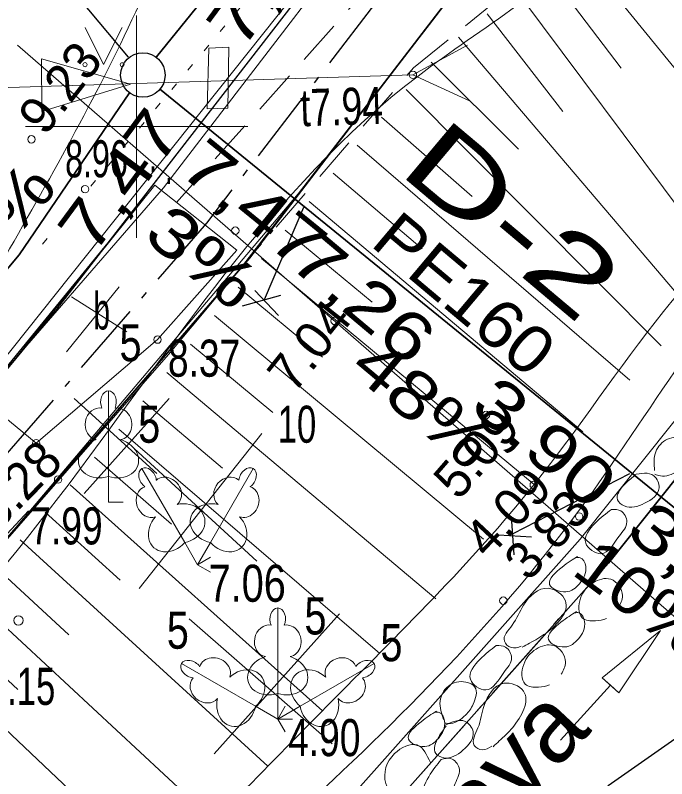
# Model space of a CAD drawing. Extents: x -1320 to -1174, y 762 to 862.
# Drawn here: x -1247.14 to -1238.36, y 811.79 to 822.09 of the extents above; entities that cross this region are included whole.
import ezdxf
from ezdxf.enums import TextEntityAlignment as Align

# ---------------------------------------------------------------- set-up
doc = ezdxf.new("R2010")
doc.units = 0
doc.header["$LTSCALE"] = 0.2
for name, pattern in [('DOT_DASHED', [7.7, 5, -1.2, 0.3, -1.2]), ('DOTTED', [1.5, 0.3, -1.2]), ('MEDIUM_DASHED', [4.5, 3, -1.5])]:
    doc.linetypes.add(name, pattern=pattern)
for name, color, linetype, lineweight in [('1', 7, 'Continuous', 13), ('11', 7, 'Continuous', 35), ('12', 7, 'Continuous', 13), ('19', 7, 'Continuous', 25), ('25', 7, 'Continuous', 13), ('28', 7, 'Continuous', 13), ('3', 7, 'Continuous', 13), ('30', 7, 'Continuous', 13), ('35', 7, 'Continuous', 25), ('4', 7, 'Continuous', 13), ('5', 7, 'Continuous', 13), ('55', 7, 'Continuous', 13), ('56', 7, 'Continuous', 13), ('57', 7, 'DOTTED', 13), ('6', 7, 'Continuous', 13), ('61', 7, 'Continuous', 13), ('62', 7, 'Continuous', 13), ('63', 7, 'Continuous', 13)]:
    doc.layers.add(name, color=color, linetype=linetype, lineweight=lineweight)
for name, color, linetype in [('15', 7, 'Continuous'), ('27', 7, 'Continuous'), ('8', 7, 'Continuous')]:
    doc.layers.add(name, color=color, linetype=linetype)

msp = doc.modelspace()

# ---------------------------------------------------------------- linework, layer by layer
at = {"layer": '1'}
for p, q in [((-1239.583, 823.017), (-1236.735, 819.506)), ((-1239.977, 822.71), (-1238.971, 821.376)), ((-1240.377, 822.41), (-1237.544, 818.612)), ((-1240.776, 822.109), (-1239.755, 820.789)), ((-1241.164, 821.793), (-1238.014, 818.09)), ((-1247.111, 821.685), (-1235.538, 811.611)), ((-1241.532, 821.455), (-1240.352, 820.28)), ((-1241.871, 821.088), (-1238.432, 817.627)), ((-1242.202, 820.713), (-1240.977, 819.642)), ((-1242.53, 820.335), (-1238.852, 817.164)), ((-1242.855, 819.955), (-1241.653, 818.938)), ((-1243.178, 819.573), (-1239.485, 816.469)), ((-1243.499, 819.19), (-1242.327, 818.215)), ((-1243.818, 818.805), (-1240.142, 815.757)), ((-1244.137, 818.42), (-1242.998, 817.476)), ((-1244.456, 818.036), (-1240.825, 815.021)), ((-1244.776, 817.651), (-1243.669, 816.729)), ((-1245.097, 817.268), (-1241.468, 814.213)), ((-1245.419, 816.885), (-1244.345, 815.976)), ((-1245.744, 816.505), (-1242.224, 813.478)), ((-1246.072, 816.127), (-1245.032, 815.219)), ((-1246.402, 815.753), (-1242.999, 812.703)), ((-1246.737, 815.381), (-1245.727, 814.465)), ((-1247.074, 815.011), (-1243.736, 811.955)), ((-1247.412, 814.643), (-1246.417, 813.726)), ((-1247.751, 814.276), (-1244.455, 811.216)), ((-1248.092, 813.91), (-1247.108, 812.991)), ((-1248.434, 813.546), (-1245.172, 810.47))]:
    msp.add_line(p, q, dxfattribs=at)
msp.add_spline([(-1235.8, 825.801), (-1237.913, 825.174), (-1239.203, 823.346), (-1241.709, 821.268), (-1246.557, 815.58), (-1256.526, 805.053), (-1260.592, 799.147), (-1261.416, 795.29), (-1262.742, 791.444), (-1262.206, 785.139)], degree=3, dxfattribs=at)
at = {"layer": '11'}
for points in [[(-1245.235, 821.525), (-1243.382, 823.815), (-1241.289, 826.563)], [(-1253.071, 812.055), (-1251.479, 813.616), (-1247.089, 818.854), (-1245.599, 821.041)]]:
    msp.add_lwpolyline(points, dxfattribs=at)
at = {"layer": '19', "lineweight": 13}
msp.add_spline([(-1253.457, 785.393), (-1253.726, 794.104), (-1251.637, 801.373), (-1250.122, 804.26), (-1247.608, 807.348), (-1239.437, 815.545), (-1236.508, 819.221), (-1228.799, 821.851), (-1223.357, 826.161), (-1220.079, 827.95)], degree=3, dxfattribs=at)
at = {"layer": '25'}
for points in [[(-1245.505, 822.086), (-1245.505, 820.586), (-1245.505, 819.086)], [(-1245.505, 822.086), (-1245.505, 820.586), (-1245.505, 819.086)], [(-1247.005, 820.586), (-1245.505, 820.586), (-1244.005, 820.586)], [(-1247.005, 820.586), (-1245.505, 820.586), (-1244.005, 820.586)]]:
    msp.add_lwpolyline(points, dxfattribs=at)
at = {"layer": '28'}
msp.add_lwpolyline([(-1241.04, 821.682), (-1241.778, 821.284), (-1241.017, 820.933)], dxfattribs=at)
at = {"layer": '3'}
msp.add_line((-1251.16, 820.99), (-1241.778, 821.284), dxfattribs=at)
at = {"layer": '30'}
msp.add_spline([(-1247.278, 818.829), (-1245.467, 822.244), (-1243.421, 828.633), (-1242.663, 831.887)], degree=3, dxfattribs=at)
at = {"layer": '35'}
msp.add_lwpolyline([(-1264.692, 791.666), (-1263.121, 794.463), (-1262.995, 800.82), (-1256.407, 807.512), (-1249.819, 814.203), (-1245.888, 819.015), (-1242.275, 823.687), (-1240.604, 825.846), (-1237.968, 829.25), (-1236.511, 829.583), (-1228.03, 831.521)], dxfattribs=at)
at = {"layer": '35', "lineweight": 35}
msp.add_lwpolyline([(-1225.362, 830.487), (-1237.056, 827.834), (-1243.981, 818.809), (-1250.833, 810.905), (-1258.147, 803.474), (-1260.339, 800.099), (-1261.472, 796.156), (-1261.529, 794.093), (-1263.29, 790.894)], dxfattribs=at)
at = {"layer": '4'}
msp.add_line((-1239.786, 812.309), (-1239.113, 813.048), dxfattribs=at)
for points in [[(-1238.439, 813.788), (-1239.002, 812.947), (-1239.224, 813.15)], [(-1239.113, 813.048), (-1239.002, 812.947), (-1238.439, 813.788), (-1239.224, 813.15)]]:
    msp.add_lwpolyline(points, close=True, dxfattribs=at)
at = {"layer": '5'}
for p, q in [((-1245.884, 817.019), (-1245.884, 815.866)), ((-1245.794, 816.787), (-1245.795, 816.788)), ((-1245.432, 815.973), (-1244.856, 814.975)), ((-1243.932, 815.973), (-1244.509, 814.975)), ((-1245.884, 815.866), (-1245.884, 815.519)), ((-1245.238, 815.817), (-1245.24, 815.817)), ((-1243.971, 815.727), (-1243.971, 815.728)), ((-1245.884, 815.519), (-1245.684, 815.519)), ((-1244.856, 814.975), (-1244.682, 814.674)), ((-1244.509, 814.975), (-1244.682, 814.674)), ((-1244.682, 814.674), (-1244.509, 814.774)), ((-1244.682, 814.674), (-1244.509, 814.574)), ((-1243.601, 814.091), (-1243.601, 812.938)), ((-1243.511, 813.859), (-1243.512, 813.86)), ((-1244.9, 813.341), (-1243.902, 812.765)), ((-1244.654, 813.303), (-1244.655, 813.302)), ((-1242.302, 813.341), (-1243.301, 812.765)), ((-1242.458, 813.147), (-1242.458, 813.149)), ((-1243.601, 812.938), (-1243.601, 812.591)), ((-1243.902, 812.765), (-1243.601, 812.591)), ((-1243.301, 812.765), (-1243.601, 812.591)), ((-1243.601, 812.591), (-1243.501, 812.764)), ((-1243.601, 812.591), (-1243.401, 812.591)), ((-1243.601, 812.591), (-1243.501, 812.418))]:
    msp.add_line(p, q, dxfattribs=at)
msp.add_lwpolyline([(-1246.2, 821.922), (-1245.95, 821.422), (-1245.7, 821.922)], dxfattribs=at)
for centre, radius in [((-1246.1999, 821.4214), 0.028), ((-1245.6999, 821.4214), 0.0263), ((-1247.098, 813.9225), 0.064)]:
    msp.add_circle(centre, radius, dxfattribs=at)
for centre, major_axis, ratio, start_param, end_param in [((-1245.8836, 816.8692), (0, -0.1499), 0.707107, 3.1453698, 5.2874846), ((-1245.8845, 816.8692), (0, -0.1499), 0.707107, 0.9957007, 3.1378155), ((-1246.0123, 816.5744), (-0.0387, -0.2124), 0.861323, 3.1415927, 6.2831853), ((-1245.7558, 816.5744), (0.0387, -0.2124), 0.861323, 6.2831853, 9.424778), ((-1245.9736, 816.1121), (0.3068, 0.0951), 0.814445, 1.5707963, 4.7520146), ((-1245.7945, 816.1121), (-0.3068, 0.0951), 0.814445, 1.5311707, 4.712389), ((-1245.3567, 815.8435), (0.075, -0.1298), 0.707107, 3.1453698, 5.2874846), ((-1245.3574, 815.8431), (0.075, -0.1298), 0.707107, 0.9957007, 3.1378155), ((-1244.0067, 815.8431), (-0.075, -0.1298), 0.707107, 3.1453698, 5.2874846), ((-1244.0074, 815.8435), (-0.075, -0.1298), 0.707107, 0.9957007, 3.1378155), ((-1245.0985, 815.6521), (0.1397, -0.1646), 0.861323, 6.2831853, 9.424778), ((-1244.2656, 815.6521), (-0.1397, -0.1646), 0.861323, 3.1415927, 6.2831853), ((-1245.3208, 815.5238), (0.0727, -0.2033), 0.861323, 3.1415927, 6.2831853), ((-1244.0433, 815.5238), (-0.0727, -0.2033), 0.861323, 6.2831853, 9.424778), ((-1244.9009, 815.2324), (-0.3133, -0.071), 0.814445, 1.5311707, 4.712389), ((-1244.4632, 815.2324), (0.3133, -0.071), 0.814445, 1.5707963, 4.7520146), ((-1245.0561, 815.1428), (0.2182, 0.2358), 0.814445, 1.5707963, 4.7520146), ((-1244.308, 815.1428), (-0.2182, 0.2358), 0.814445, 1.5311707, 4.712389), ((-1243.6006, 813.9412), (0, -0.1499), 0.707107, 3.1453698, 5.2874846), ((-1243.6015, 813.9412), (0, -0.1499), 0.707107, 0.9957007, 3.1378155), ((-1243.7293, 813.6464), (-0.0387, -0.2124), 0.861323, 3.1415927, 6.2831853), ((-1243.4728, 813.6464), (0.0387, -0.2124), 0.861323, 6.2831853, 9.424778), ((-1244.7704, 813.2658), (0.1298, -0.075), 0.707107, 0.9957007, 3.1378155), ((-1244.4507, 813.2299), (0.2033, -0.0727), 0.861323, 6.2831853, 9.424778), ((-1243.6906, 813.1841), (0.3068, 0.0951), 0.814445, 1.5707963, 4.7520146), ((-1243.5115, 813.1841), (-0.3068, 0.0951), 0.814445, 1.5311707, 4.712389), ((-1242.7514, 813.2299), (-0.2033, -0.0727), 0.861323, 3.1415927, 6.2831853), ((-1242.4317, 813.2658), (-0.1298, -0.075), 0.707107, 3.1453698, 5.2874846), ((-1244.77, 813.2665), (0.1298, -0.075), 0.707107, 3.1453698, 5.2874846), ((-1244.0697, 812.9652), (-0.2358, -0.2182), 0.814445, 1.5311707, 4.712389), ((-1243.1324, 812.9652), (0.2358, -0.2182), 0.814445, 1.5707963, 4.7520146), ((-1242.4321, 813.2665), (-0.1298, -0.075), 0.707107, 0.9957007, 3.1378155), ((-1244.579, 813.0076), (0.1646, -0.1397), 0.861323, 3.1415927, 6.2831853), ((-1242.6231, 813.0076), (-0.1646, -0.1397), 0.861323, 6.2831853, 9.424778), ((-1244.1593, 812.81), (0.071, 0.3133), 0.814445, 1.5707963, 4.7520146), ((-1243.0428, 812.81), (-0.071, 0.3133), 0.814445, 1.5311707, 4.712389)]:
    msp.add_ellipse(centre, major_axis=major_axis, ratio=ratio, start_param=start_param, end_param=end_param, dxfattribs=at)
at = {"layer": '55'}
msp.add_lwpolyline([(-1279.323, 790.175), (-1264.692, 791.666), (-1263.121, 794.463), (-1263.06, 799.299), (-1247.785, 816.834), (-1237.845, 829.32), (-1225.799, 831.912), (-1223.768, 834.184)], dxfattribs=at)
at = {"layer": '56'}
msp.add_lwpolyline([(-1247.583, 816.91), (-1246.86, 816.313), (-1245.222, 817.711), (-1244.154, 818.919), (-1245.261, 819.794)], close=True, dxfattribs=at)
at = {"layer": '57'}
msp.add_line((-1246.776, 819.001), (-1237.687, 829.874), dxfattribs=at)
at = {"layer": '6'}
for centre in [(-1241.778, 821.2841), (-1246.9232, 820.4134), (-1246.2, 819.7412), (-1244.173, 819.1811), (-1242.833, 817.9632), (-1245.222, 817.7112), (-1240.792, 816.6942), (-1246.86, 816.3132), (-1246.564, 815.8232), (-1240.149, 815.7502), (-1239.537, 815.3252), (-1240.559, 814.1892)]:
    msp.add_circle(centre, 0.05, dxfattribs=at)
at = {"layer": '61'}
msp.add_lwpolyline([(-1249.819, 814.203), (-1246.581, 818.124), (-1237.968, 829.25), (-1225.679, 832.058)], dxfattribs=at)
at = {"layer": '62'}
msp.add_spline([(-1254.434, 786.21), (-1255.853, 794.247), (-1253.373, 799.783), (-1252.196, 801.907), (-1252.103, 801.965), (-1250.675, 804.058), (-1247.791, 807.511), (-1245.419, 810.213), (-1244.186, 811.494), (-1242.939, 812.764), (-1240.149, 815.75), (-1236.129, 820.169), (-1233.075, 822.242), (-1235.394, 825.816)], degree=3, dxfattribs=at)
at = {"layer": '63', "lineweight": 25}
for p, q in [((-1245.613, 821.52), (-1246.524, 822.613)), ((-1243.252, 819.493), (-1243.785, 818.247)), ((-1243.91, 818.374), (-1243.59, 818.036)), ((-1243.565, 818.305), (-1244.081, 818.163)), ((-1238.858, 815.9), (-1240.429, 815.09)), ((-1240.453, 815.323), (-1240.416, 814.806)), ((-1240.622, 815.076), (-1240.179, 815.051))]:
    msp.add_line(p, q, dxfattribs=at)
at = {"layer": '63', "lineweight": 35}
msp.add_line((-1245.197, 821.093), (-1238.151, 815.361), dxfattribs=at)
at = {"layer": '63'}
for p, q in [((-1245.74, 818.424), (-1246.449, 817.546)), ((-1246.381, 818.289), (-1245.638, 817.816)), ((-1246.349, 816.919), (-1245.234, 815.905)), ((-1245.065, 816.919), (-1246.214, 815.635)), ((-1243.815, 816.446), (-1245.47, 814.351)), ((-1245.538, 816.243), (-1243.882, 814.723)), ((-1242.767, 814.013), (-1244.457, 812.121)), ((-1244.795, 813.946), (-1242.869, 812.256))]:
    msp.add_line(p, q, dxfattribs=at)
at = {"layer": '63', "lineweight": 25}
msp.add_lwpolyline([(-1251.428, 785.238), (-1264.287, 784.95), (-1270.386, 788.761), (-1278.142, 789.522), (-1278.429, 820.376), (-1260.692, 834.371), (-1258.181, 840.695), (-1250.014, 845.483), (-1229.719, 840.992), (-1227.821, 835.408), (-1218.992, 825.806), (-1239.144, 811.691), (-1246.246, 803.626), (-1250.024, 795.415), (-1251.371, 785.665)], close=True, dxfattribs=at)
at = {"layer": '63', "linetype": 'MEDIUM_DASHED'}
for points in [[(-1225.119, 832.074), (-1232.655, 830.279), (-1235.176, 829.494), (-1238.254, 828.059), (-1240.45, 824.627), (-1244.967, 819.561)], [(-1265.079, 785.987), (-1263.807, 789.442), (-1261.536, 795.397), (-1260.86, 799.605), (-1256.627, 805.136), (-1246.564, 815.823), (-1241.769, 821.378), (-1239.214, 823.453), (-1237.177, 827.558), (-1234.848, 828.79), (-1231.517, 829.195), (-1224.557, 831.447)]]:
    msp.add_lwpolyline(points, dxfattribs=at)
at = {"layer": '63'}
for points in [[(-1262.966, 796.388), (-1261.719, 800.729), (-1259.323, 804.418), (-1255.629, 808.17), (-1251.935, 811.923), (-1248.539, 815.84), (-1245.143, 819.757), (-1241.53, 824.466), (-1237.916, 829.176), (-1231.805, 830.562), (-1225.694, 831.949), (-1225.362, 830.487), (-1237.053, 827.834), (-1240.518, 823.322), (-1243.326, 819.676), (-1247.407, 814.857), (-1250.833, 810.905), (-1254.833, 806.84), (-1258.147, 803.474), (-1260.348, 800.104), (-1261.483, 796.15)], [(-1261.483, 796.15), (-1260.348, 800.104), (-1258.147, 803.474), (-1257.342, 804.291), (-1256.78, 804.862), (-1256.04, 805.612), (-1253.626, 808.067), (-1251.48, 810.249), (-1250.651, 811.111), (-1250.414, 811.388), (-1248.806, 813.242), (-1245.075, 817.511), (-1244.093, 818.684), (-1242.558, 820.667), (-1241.555, 821.963), (-1239.557, 824.569), (-1237.053, 827.834), (-1230.901, 829.229)], [(-1231.863, 823.367), (-1235.734, 819.766), (-1239.521, 815.019), (-1242.918, 811.201), (-1245.916, 807.839), (-1248.699, 804.681), (-1251.078, 801.983), (-1252.85, 799.838), (-1253.787, 798.196), (-1254.328, 797.239), (-1254.328, 797.239), (-1255.102, 794.624)]]:
    msp.add_lwpolyline(points, dxfattribs=at)
at = {"layer": '63', "linetype": 'DOT_DASHED', "lineweight": 25}
for points in [[(-1225.528, 831.218), (-1237.486, 828.505), (-1244.562, 819.283), (-1251.384, 811.414), (-1258.735, 803.946), (-1261.029, 800.414), (-1262.219, 796.272), (-1262.274, 794.295), (-1264.33, 790.56), (-1266.742, 787.222)], [(-1254.918, 786.26), (-1254.605, 794.542), (-1253.865, 797.042), (-1252.437, 799.553), (-1250.698, 801.658), (-1245.95, 807.041), (-1239.139, 814.697), (-1235.363, 819.429), (-1232.239, 822.444), (-1231.619, 822.931), (-1231.44, 822.991), (-1229.31, 823.677), (-1223.125, 826.536)]]:
    msp.add_lwpolyline(points, dxfattribs=at)
at = {"layer": '63', "lineweight": 35}
msp.add_lwpolyline([(-1254.918, 786.26), (-1254.605, 794.542), (-1253.865, 797.042), (-1252.437, 799.553), (-1251.568, 800.606), (-1250.698, 801.658), (-1248.324, 804.35), (-1245.95, 807.041), (-1242.544, 810.869), (-1239.139, 814.697), (-1237.251, 817.063), (-1235.363, 819.429), (-1233.801, 820.936), (-1232.239, 822.444), (-1231.619, 822.931), (-1229.31, 823.677), (-1223.125, 826.536)], dxfattribs=at)
at = {"layer": '63'}
for points in [[(-1244.529, 821.642), (-1244.554, 820.823), (-1244.276, 820.836), (-1244.259, 821.656)], [(-1245.589, 821.158), (-1246.786, 821.499), (-1246.785, 820.79)]]:
    msp.add_lwpolyline(points, close=True, dxfattribs=at)
at = {"layer": '63', "lineweight": 25}
msp.add_circle((-1245.4202, 821.2809), 0.3, dxfattribs=at)
at = {"layer": '63'}
for points in [[(-1238.519, 815.945), (-1238.503, 816.198), (-1238.346, 816.368), (-1238.105, 816.363), (-1238.002, 816.267), (-1238.082, 816.05), (-1238.217, 815.931), (-1238.44, 815.872), (-1238.517, 815.896)], [(-1238.806, 815.887), (-1238.528, 815.872), (-1238.458, 815.711), (-1238.653, 815.503), (-1238.927, 815.467), (-1239.019, 815.551), (-1238.925, 815.756), (-1238.791, 815.874)], [(-1239.101, 815.42), (-1239.321, 815.235), (-1239.448, 814.966), (-1239.242, 814.823), (-1238.998, 815.059), (-1238.893, 815.253), (-1238.974, 815.4), (-1239.101, 815.42)], [(-1239.557, 814.786), (-1239.766, 814.643), (-1239.934, 814.408), (-1239.716, 814.308), (-1239.532, 814.417), (-1239.448, 814.652), (-1239.523, 814.769), (-1239.582, 814.769)], [(-1239.009, 814.091), (-1238.951, 814.257), (-1239.111, 814.478), (-1239.349, 814.431), (-1239.516, 814.224), (-1239.495, 813.959), (-1239.317, 813.916), (-1239.166, 813.947)], [(-1240.316, 813.575), (-1240.454, 813.557), (-1240.545, 813.642), (-1240.439, 813.858), (-1240.286, 814.13), (-1239.954, 814.357), (-1239.722, 814.188), (-1239.982, 813.751), (-1240.204, 813.617), (-1240.303, 813.562)], [(-1239.572, 814.042), (-1239.781, 813.899), (-1239.949, 813.664), (-1239.731, 813.564), (-1239.547, 813.673), (-1239.463, 813.908), (-1239.538, 814.025), (-1239.597, 814.025)], [(-1240.655, 813.582), (-1240.875, 813.397), (-1241.002, 813.128), (-1240.796, 812.985), (-1240.552, 813.221), (-1240.447, 813.415), (-1240.528, 813.562), (-1240.655, 813.582)], [(-1239.777, 813.196), (-1239.719, 813.362), (-1239.879, 813.583), (-1240.117, 813.536), (-1240.284, 813.329), (-1240.263, 813.064), (-1240.085, 813.021), (-1239.934, 813.052)], [(-1241.364, 812.584), (-1241.411, 812.834), (-1241.3, 813.037), (-1241.065, 813.091), (-1240.942, 813.023), (-1240.966, 812.793), (-1241.068, 812.645), (-1241.27, 812.533), (-1241.35, 812.537)], [(-1240.712, 812.227), (-1240.842, 812.176), (-1240.951, 812.236), (-1240.901, 812.472), (-1240.819, 812.773), (-1240.553, 813.074), (-1240.286, 812.967), (-1240.432, 812.48), (-1240.614, 812.296), (-1240.697, 812.218)], [(-1241.46, 812.699), (-1241.669, 812.556), (-1241.837, 812.321), (-1241.619, 812.221), (-1241.435, 812.33), (-1241.351, 812.565), (-1241.426, 812.682), (-1241.485, 812.682)], [(-1241.346, 812.506), (-1241.073, 812.56), (-1240.966, 812.421), (-1241.104, 812.171), (-1241.361, 812.069), (-1241.471, 812.128), (-1241.43, 812.35), (-1241.329, 812.497)], [(-1241.543, 812.004), (-1241.719, 812.242), (-1242.025, 812.125), (-1242.144, 811.724), (-1241.945, 811.492), (-1241.633, 811.545)], [(-1241.397, 812.046), (-1241.565, 811.813), (-1241.623, 811.521), (-1241.388, 811.433), (-1241.209, 811.721), (-1241.155, 811.935), (-1241.269, 812.058), (-1241.397, 812.046)]]:
    msp.add_spline(points, degree=3, dxfattribs=at)

# ---------------------------------------------------------------- texts
at = {"layer": '11'}
for s, height, rotation, width, p in [('t7.94', 0.5, 1.795, 0.75, (-1242.7328, 820.6057)), ('D-2', 1, 319.946, 1.5, (-1240.7593, 818.9345))]:
    msp.add_text(s, height=height, rotation=rotation, dxfattribs=dict(at, width=width)).set_placement(p, align=Align.CENTER)
at = {"layer": '12'}
for s, width, p in [(' 5', 0.8, (-1245.884, 817.419)), (' 5', 0.8, (-1245.632, 816.32)), (' 10', 0.7, (-1243.732, 816.32)), (' 5', 0.8, (-1243.39, 813.733)), (' 5', 0.8, (-1245.246, 813.541)), (' 5', 0.8, (-1242.365, 813.372))]:
    msp.add_text(s, height=0.5, dxfattribs=dict(at, width=width)).set_placement(p)
at = {"layer": '15', "width": 0.6}
msp.add_text('b', height=0.5, dxfattribs=at).set_placement((-1246.087, 817.848))
at = {"layer": '27'}
msp.add_text('upe Íekava', height=1, rotation=46.796, dxfattribs=at).set_placement((-1243.835, 807.665))
at = {"layer": '63'}
for s, rotation, width, p in [('7,47', 53.597, 1.25, (-1243.4691, 822.4416)), ('7,47', 53.597, 1.25, (-1245.4741, 819.6726)), ('7,47', 320.831, 1.3, (-1244.1251, 819.2912)), ('1,6%', 49.693, 1.2, (-1247.3067, 818.8625)), ('3%', 320.831, 1.3, (-1244.8156, 818.5791)), ('PE160', 319.946, 1.1, (-1241.2879, 818.0812)), ('7,26', 319.946, 1.3, (-1242.6524, 818.0283)), ('48%', 319.946, 1.25, (-1241.8374, 816.6061)), ('3,90', 319.946, 1.3, (-1240.2054, 816.0793)), ('3,80', 319.946, 1.35, (-1238.0789, 814.3724)), ('10%', 323.374, 1.15, (-1238.8684, 813.9721))]:
    msp.add_text(s, height=0.64, rotation=rotation, dxfattribs=dict(at, width=width)).set_placement(p, align=Align.CENTER)
at = {"layer": '8'}
for s, rotation, p in [(' 9.23', 52.106, (-1246.855, 820.298)), (' 7.04', 51.541, (-1243.5, 816.822)), (' 5.09', 49.117, (-1241.283, 815.388)), (' 8.28', 45.877, (-1247.509, 814.978)), (' 4.09', 46.86, (-1240.891, 814.603)), (' 3.83', 47.809, (-1240.342, 814.296))]:
    msp.add_text(s, height=0.5, rotation=rotation, dxfattribs=at).set_placement(p)
for s, width, p in [('8.96', 0.65, (-1246.469, 819.901)), ('.', 0.5, (-1245.33, 819.972)), ('.', 0.5, (-1245.116, 819.812)), (' 8.37', 0.75, (-1245.222, 817.211)), (' 7.99', 0.75, (-1247.078, 814.948)), (' 7.06', 0.8, (-1244.682, 814.174)), (' 8.15', 0.7, (-1247.642, 812.783)), (' 4.90', 0.75, (-1243.601, 812.091))]:
    msp.add_text(s, height=0.5, dxfattribs=dict(at, width=width)).set_placement(p)

doc.saveas('drawing.dxf')
